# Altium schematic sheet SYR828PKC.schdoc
size 127 x 101 mm
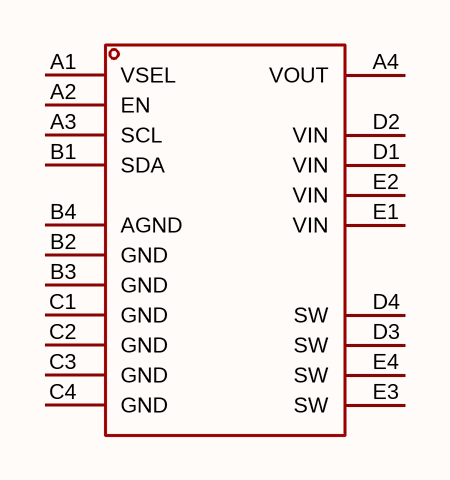
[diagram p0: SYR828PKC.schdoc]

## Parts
U?  syr828pkc  [WLCSP-20_L2.0-W1.6-P0.40-R5-C4-BL]  (value not drawn)

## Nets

Not connected (* = marked no-connect by the designer): U? A1(VSEL) A2(EN) A3(SCL) A4(VOUT) B1(SDA) B2(GND) B3(GND) B4(AGND) C1(GND) C2(GND) C3(GND) C4(GND) D1(VIN) D2(VIN) D3(SW) D4(SW) E1(VIN) E2(VIN) E3(SW) E4(SW)

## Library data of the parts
U? = syr828pkc: 功能类型:降压型;工作电压:2.6V~5.5V;输出电压:712.5mV~1.5V;输出电流:6A;输出类型:可调;; Manufacturer: Silergy(矽力杰); AddInBom: yes; ModelId: 7afb8f88926b4e64a2d440c793ccb6a5; ModelName: WLCSP-20_L2.0-W1.6-H0.6-P0.40-R5-C4-BL; ModelTransform: 78.74,62.992,0,0,0,0,-0.001,-0.003,0; Function: 降压型; Output Current: 6A; Frequency - Switching: 2.4MHz; Synchronous Rectifier: 是; Number of Outputs: 1; Topology: 降压式; Quiescent Current: 65uA; Switch tube (built-in/external): 内置; Output Type: 可调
